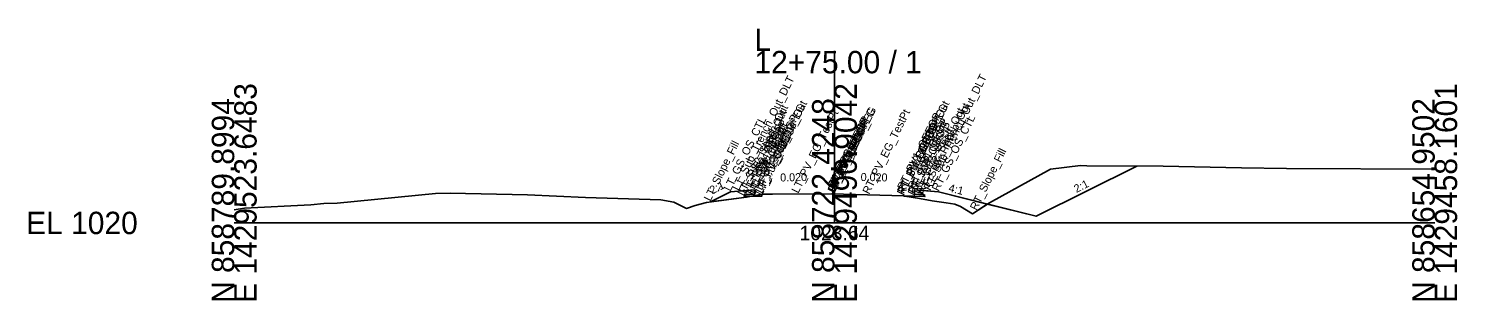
# Model space of a CAD drawing. Extents: x -26 to 176, y -10 to 13058.
# Drawn here: x -25.7 to 152.8, y 2490.3 to 2524.3 of the extents above; entities that cross this region are included whole.
import ezdxf

# ---------------------------------------------------------------- set-up
doc = ezdxf.new("R2010")
doc.units = 0
for name, color, linetype in [('Default', 7, 'Continuous'), ('Exist Cross Section Cell', 7, 'Continuous'), ('Exist XS Center Line Elevation Label', 7, 'Continuous'), ('Exist XS Ground Line', 7, 'Continuous'), ('Old_Level_50', 7, 'Continuous'), ('Prop CMT Pvmt Course 1', 7, 'Continuous'), ('Prop CMT Pvmt Course 2', 7, 'Continuous'), ('Prop CMT Pvmt Surface Shoulder', 7, 'Continuous'), ('Prop CMT Pvmt Wedge Surface 1', 7, 'Continuous'), ('Prop CMT Pvmt Wedge Surface 2', 7, 'Continuous'), ('Prop CMT Shld Paved Course 1', 7, 'Continuous'), ('Prop CMT Shld Paved Course 2', 7, 'Continuous'), ('Prop CMT Slope Grass', 7, 'Continuous'), ('Prop CMT Subgrade Earthwork', 7, 'Continuous'), ('Prop XS Dump Level', 7, 'Continuous'), ('Prop XS SE Text', 7, 'Continuous'), ('Prop XS Side Slope Text', 7, 'Continuous')]:
    doc.layers.add(name, color=color, linetype=linetype)

msp = doc.modelspace()

# ---------------------------------------------------------------- linework, layer by layer
at = {"layer": 'Exist Cross Section Cell'}
for p, q in [((75, 2500), (75, 2521.51)), ((0, 2500), (75, 2500)), ((75, 2500), (150, 2500))]:
    msp.add_line(p, q, dxfattribs=at)
at = {"layer": 'Exist XS Ground Line'}
msp.add_lwpolyline([(0, 2501.63), (1.28, 2501.83), (9.57, 2502.27), (11.2, 2502.43), (12.85, 2502.47), (25.15, 2503.67), (27, 2503.72), (36.65, 2503.51), (43.88, 2503.19), (53.32, 2502.88), (54.93, 2502.61), (56.53, 2501.81), (57.6, 2502.2), (59.02, 2502.57), (63.99, 2503.24), (65.94, 2503.6), (67.24, 2503.61), (74.69, 2503.65), (75, 2503.64), (76.15, 2503.61), (83.67, 2503.37), (85.63, 2503.04), (87.2, 2502.77), (88.94, 2502.51), (90.06, 2502.33), (90.74, 2502.06), (92.23, 2501.14), (94.36, 2502.52), (102.01, 2506.74), (105.73, 2507.17), (106.54, 2507.15), (116.08, 2507.11), (125.87, 2506.9), (131.47, 2506.82), (150, 2506.72)], dxfattribs=at)
at = {"layer": 'Old_Level_50'}
for points in [[(94.36, 2502.52), (102.01, 2506.74), (105.73, 2507.17), (106.54, 2507.15), (112.78, 2507.12), (100.19, 2500.83), (94.1, 2502.35)], [(102.01, 2506.74), (105.73, 2507.17), (106.54, 2507.15), (112.78, 2507.12), (100.19, 2500.83), (94.1, 2502.35), (94.36, 2502.52)], [(102.01, 2506.74), (105.73, 2507.17), (106.54, 2507.15), (112.78, 2507.12), (100.19, 2500.83), (94.1, 2502.35), (94.36, 2502.52)], [(59.51, 2502.64), (63.99, 2503.24), (64.42, 2503.31), (63.69, 2503.3), (63.95, 2503.56), (64.45, 2503.57), (65, 2503.58), (65, 2504.12), (62, 2503.88)], [(64.45, 2503.57), (65, 2503.58), (65, 2504.12), (62, 2503.88), (59.51, 2502.64), (63.99, 2503.24), (64.42, 2503.31), (63.69, 2503.3), (63.95, 2503.56)], [(64.45, 2503.57), (65, 2503.58), (65, 2504.12), (62, 2503.88), (59.51, 2502.64), (63.99, 2503.24), (64.42, 2503.31), (63.69, 2503.3), (63.95, 2503.56)], [(64.42, 2503.31), (65.94, 2503.6), (65.94, 2503.35), (65, 2503.33)], [(65, 2503.33), (65.94, 2503.35), (65.94, 2503.6), (64.42, 2503.31)], [(65, 2503.33), (65.94, 2503.35), (65.94, 2503.6), (64.42, 2503.31)], [(83.79, 2503.35), (83.67, 2503.35), (83.65, 2503.37), (83.67, 2503.37)], [(83.67, 2503.37), (83.79, 2503.35), (83.67, 2503.35), (83.65, 2503.37)], [(83.67, 2503.37), (83.79, 2503.35), (83.67, 2503.35), (83.65, 2503.37)], [(85, 2504.12), (88, 2503.88), (94.1, 2502.35), (92.23, 2501.14), (90.74, 2502.06), (90.06, 2502.33), (88.94, 2502.51), (87.2, 2502.77), (85.63, 2503.04), (83.79, 2503.35), (85, 2503.33), (86.31, 2503.3), (86.05, 2503.56), (85.55, 2503.57), (85, 2503.58)], [(85.55, 2503.57), (85, 2503.58), (85, 2504.12), (88, 2503.88), (94.1, 2502.35), (92.23, 2501.14), (90.74, 2502.06), (90.06, 2502.33), (88.94, 2502.51), (87.2, 2502.77), (85.63, 2503.04), (83.79, 2503.35), (85, 2503.33), (86.31, 2503.3), (86.05, 2503.56)], [(85.55, 2503.57), (85, 2503.58), (85, 2504.12), (88, 2503.88), (94.1, 2502.35), (92.23, 2501.14), (90.74, 2502.06), (90.06, 2502.33), (88.94, 2502.51), (87.2, 2502.77), (85.63, 2503.04), (83.79, 2503.35), (85, 2503.33), (86.31, 2503.3), (86.05, 2503.56)]]:
    msp.add_lwpolyline(points, close=True, dxfattribs=at)
at = {"layer": 'Prop CMT Pvmt Course 1'}
for points in [[(65, 2504.12), (65, 2503.58)], [(85, 2504.12), (85, 2503.58)]]:
    msp.add_lwpolyline(points, dxfattribs=at)
at = {"layer": 'Prop CMT Pvmt Course 2'}
for points in [[(65, 2503.33), (65.94, 2503.35)], [(65.94, 2503.35), (65.94, 2503.6)], [(85, 2503.33), (83.67, 2503.35)]]:
    msp.add_lwpolyline(points, dxfattribs=at)
at = {"layer": 'Prop CMT Pvmt Surface Shoulder'}
for points in [[(65, 2504.12), (65, 2504.12)], [(85, 2504.12), (85, 2504.12)]]:
    msp.add_lwpolyline(points, dxfattribs=at)
at = {"layer": 'Prop CMT Pvmt Wedge Surface 1'}
for points in [[(65, 2503.58), (65, 2504.12)], [(85, 2503.58), (85, 2504.12)]]:
    msp.add_lwpolyline(points, dxfattribs=at)
at = {"layer": 'Prop CMT Pvmt Wedge Surface 2'}
for points in [[(65, 2503.58), (65, 2504.12)], [(85, 2503.58), (85, 2504.12)]]:
    msp.add_lwpolyline(points, dxfattribs=at)
at = {"layer": 'Prop CMT Shld Paved Course 1'}
for points in [[(64.45, 2503.57), (65, 2503.58)], [(65, 2504.12), (65, 2504.12)], [(65, 2503.58), (65, 2504.12)], [(85, 2504.12), (85, 2504.12)], [(85, 2503.58), (85, 2504.12)], [(85.55, 2503.57), (85, 2503.58)]]:
    msp.add_lwpolyline(points, dxfattribs=at)
at = {"layer": 'Prop CMT Shld Paved Course 2'}
for points in [[(65, 2503.58), (64.45, 2503.57), (63.95, 2503.56), (63.69, 2503.3)], [(63.69, 2503.3), (65, 2503.33)], [(85, 2503.58), (85.55, 2503.57), (86.05, 2503.56), (86.31, 2503.3)], [(86.31, 2503.3), (85, 2503.33)]]:
    msp.add_lwpolyline(points, dxfattribs=at)
at = {"layer": 'Prop CMT Slope Grass'}
for p, q in [((100.19, 2500.83), (112.78, 2507.12)), ((88, 2503.88), (100.19, 2500.83))]:
    msp.add_line(p, q, dxfattribs=at)
for points in [[(65, 2504.12), (62, 2503.88), (59.51, 2502.64)], [(85, 2504.12), (88, 2503.88)]]:
    msp.add_lwpolyline(points, dxfattribs=at)
at = {"layer": 'Prop CMT Subgrade Earthwork'}
for points in [[(65, 2503.33), (63.69, 2503.3)], [(65.94, 2503.35), (65, 2503.33)], [(65.94, 2503.35), (65.96, 2503.6)], [(83.67, 2503.35), (83.65, 2503.37)], [(83.67, 2503.35), (85, 2503.33)], [(85, 2503.33), (86.31, 2503.3)]]:
    msp.add_lwpolyline(points, dxfattribs=at)

# ---------------------------------------------------------------- texts
at = {"layer": 'Default'}
msp.add_text('-', height=0.0001, dxfattribs=at).set_placement((0, 2500))
at = {"layer": 'Exist Cross Section Cell'}
for s, p in [('L', (65, 2521.51)), ('12+75.00 / 1', (65, 2518.71)), ('EL 1020', (-26, 2498.6))]:
    msp.add_text(s, height=2.8, dxfattribs=at).set_placement(p)
for s, p in [('E 1429523.6483', (2.8, 2490)), ('E 1429490.9042', (77.8, 2490)), ('E 1429458.1601', (152.8, 2490)), ('N 858789.8994', (0, 2490)), ('N 858722.4248', (75, 2490)), ('N 858654.9502', (150, 2490))]:
    msp.add_text(s, height=2.8, rotation=90, dxfattribs=at).set_placement(p)
at = {"layer": 'Exist XS Center Line Elevation Label'}
msp.add_text('1023.64', height=1.8, dxfattribs=at).set_placement((70.65, 2497.84))
msp.add_text('1023.64', height=1.8, dxfattribs=at).set_placement((70.65, 2497.84))
msp.add_text('1023.64', height=1.8, dxfattribs=at).set_placement((70.65, 2497.84))
at = {"layer": 'Prop XS Dump Level'}
for s, p in [('LT_Sub_Trench_Out_DLT', (63.03, 2503.96)), ('RT_Sub_Trench_Out_DLT', (86.97, 2503.96)), ('LT_Sub_Trench_Out', (63.69, 2503.3)), ('LT_PS2_Shelf_Out', (63.95, 2503.56)), ('LT_PV_OEEOP_EG', (65.94, 2503.6)), ('LT_PV_Sub_Tie_Out', (65.96, 2503.6)), ('LT_PV_EG_TestPt', (70.47, 2503.63)), ('RT_PV_IEEOP_EG', (75, 2503.64)), ('LT_PV_IEEOP_EG', (75, 2503.64)), ('RT_PV_EG_TestPt', (79.33, 2503.51)), ('RT_PV_Sub_Tie_Out', (83.65, 2503.37)), ('RT_PV_OEEOP_EG', (83.67, 2503.37)), ('RT_PV1_OEEOP', (83.67, 2504.02)), ('RT_PS2_Shelf_Out', (86.05, 2503.56)), ('RT_Sub_Trench_Out', (86.31, 2503.3)), ('LT_GS_OS_CTL', (62, 2503.88)), ('LT_PS2_OEOP', (64.45, 2503.57)), ('LT_PV1_OEOT', (65, 2504.12)), ('LT_PS1_OEOP', (65, 2504.12)), ('LT_PV2_OEOT', (65, 2503.58)), ('LT_Sub_OEOT', (65, 2503.33)), ('LT_PV1_OEEOP', (65.94, 2504.01)), ('LT_PV2_OEEOP', (65.94, 2503.6)), ('LT_Sub_OEEOP', (65.94, 2503.35)), ('RT_PV1_IEEOP', (75, 2504.19)), ('LT_PV1_IEEOP', (75, 2504.19)), ('RT_PV2_IEEOP', (75, 2503.78)), ('LT_PV2_IEEOP', (75, 2503.78)), ('RT_PV2_OEEOP', (83.67, 2503.6)), ('RT_Sub_OEEOP', (83.67, 2503.35)), ('RT_PV1_OEOT', (85, 2504.12)), ('RT_PS1_OEOP', (85, 2504.12)), ('RT_PV2_OEOT', (85, 2503.58)), ('RT_Sub_OEOT', (85, 2503.33)), ('RT_PS2_OEOP', (85.55, 2503.57)), ('RT_GS_OS_CTL', (88, 2503.88)), ('LT_Slope_Fill', (59.51, 2502.64)), ('PV1_PGL', (75, 2504.32)), ('PV2_PGL', (75, 2503.78)), ('RT_Slope_Fill', (92.77, 2501.49))]:
    msp.add_text(s, height=1, rotation=63.5833, dxfattribs=at).set_placement(p)
at = {"layer": 'Prop XS SE Text'}
for rotation, p in [(1.1458, (68.23, 2505.18)), (358.8542, (78.27, 2505.25))]:
    msp.add_text('0.020', height=1, rotation=rotation, dxfattribs=at).set_placement(p)
at = {"layer": 'Prop XS Side Slope Text'}
for s, rotation, p in [('2:1', 26.5651, (59.71, 2503.57)), ('2:1', 26.5651, (105.23, 2503.74)), ('4:1', 345.9638, (89.19, 2503.94))]:
    msp.add_text(s, height=1, rotation=rotation, dxfattribs=at).set_placement(p)

doc.saveas('drawing.dxf')
